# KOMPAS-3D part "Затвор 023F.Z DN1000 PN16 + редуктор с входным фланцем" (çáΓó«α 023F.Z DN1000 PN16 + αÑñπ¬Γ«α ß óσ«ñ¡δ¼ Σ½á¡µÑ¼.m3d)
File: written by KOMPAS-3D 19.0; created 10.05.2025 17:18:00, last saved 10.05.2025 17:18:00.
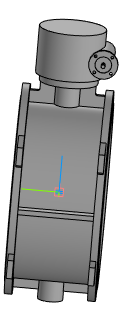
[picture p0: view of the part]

Document properties: Полное имя файла: Затвор 023F.Z DN1000 PN16 + редуктор с входным фланцем.a3d

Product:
- Part/product: Затвор 023F.Z DN1000 PN16 + редуктор с входным фланцем
    Масса: 1596.25

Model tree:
1. Операция без истории:1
